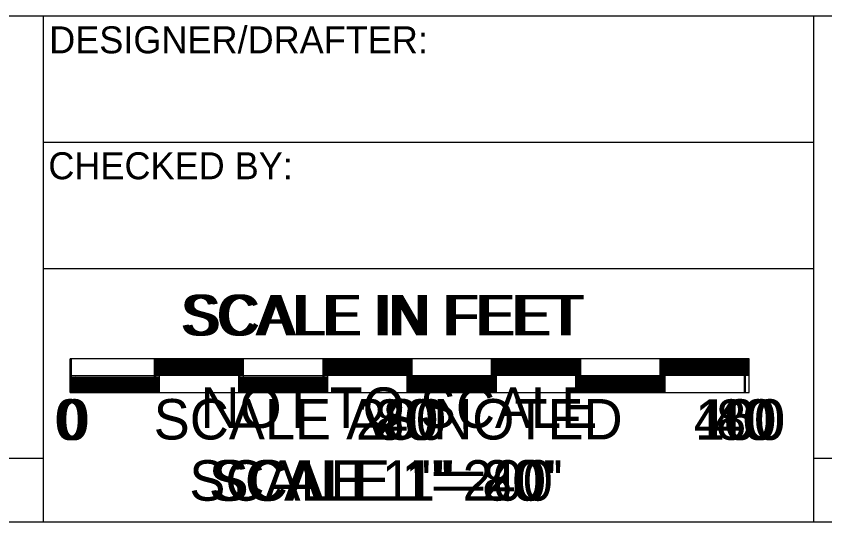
# Model space of a CAD drawing. Extents: x 0 to 2011, y -71 to 1183.
# Drawn here: x 341.3 to 437.3, y -1 to 59 of the extents above; entities that cross this region are included whole.
import ezdxf

# ---------------------------------------------------------------- set-up
doc = ezdxf.new("R2010")
doc.units = 0
for name, color, linetype in [('CT_Border_Perimeter_Shape', 7, 'Continuous'), ('CT_Scale_1_Inch_Equals_200_Feet', 7, 'Continuous'), ('CT_Scale_1_Inch_Equals_20_Feet', 7, 'Continuous'), ('CT_Scale_1_Inch_Equals_40_Feet', 7, 'Continuous'), ('CT_Scale_1_Inch_Equals_80_Feet', 7, 'Continuous'), ('CT_Scale_as_Noted', 7, 'Continuous'), ('CT_Title_Block_Linework', 7, 'Continuous'), ('CT_Title_Block_Text', 7, 'Continuous')]:
    doc.layers.add(name, color=color, linetype=linetype)

msp = doc.modelspace()

# ---------------------------------------------------------------- linework, layer by layer
at = {"layer": 'CT_Border_Perimeter_Shape'}
msp.add_lwpolyline([(0, -0.973), (1270, -0.973), (1270, 829.027), (0, 829.027)], close=True, dxfattribs=at)
at = {"layer": 'CT_Scale_1_Inch_Equals_200_Feet'}
for p, q in [((427.743, 18.378), (347.743, 18.378)), ((347.743, 14.384), (347.743, 18.378)), ((357.743, 14.385), (357.743, 18.378)), ((367.743, 18.242), (357.743, 18.242)), ((367.743, 14.385), (367.743, 18.378)), ((377.743, 14.386), (377.743, 18.378)), ((387.743, 18.242), (377.743, 18.242)), ((387.743, 14.398), (387.743, 18.378)), ((397.743, 14.398), (397.743, 18.378)), ((407.743, 18.254), (397.743, 18.254)), ((407.743, 14.388), (407.743, 18.378)), ((417.743, 14.389), (417.743, 18.378)), ((427.743, 18.254), (417.743, 18.254)), ((427.743, 14.39), (427.743, 18.378)), ((367.743, 18.118), (357.743, 18.118)), ((367.743, 17.994), (357.743, 17.994)), ((367.743, 17.87), (357.743, 17.87)), ((367.743, 17.742), (357.743, 17.742)), ((367.743, 17.618), (357.743, 17.618)), ((367.743, 17.494), (357.743, 17.494)), ((367.743, 17.37), (357.743, 17.37)), ((387.743, 18.118), (377.743, 18.118)), ((387.743, 17.994), (377.743, 17.994)), ((387.743, 17.87), (377.743, 17.87)), ((387.743, 17.742), (377.743, 17.742)), ((387.743, 17.618), (377.743, 17.618)), ((387.743, 17.494), (377.743, 17.494)), ((387.743, 17.37), (377.743, 17.37)), ((407.743, 18.13), (397.743, 18.13)), ((407.743, 18.002), (397.743, 18.002)), ((407.743, 17.878), (397.743, 17.878)), ((407.743, 17.754), (397.743, 17.754)), ((407.743, 17.63), (397.743, 17.63)), ((407.743, 17.502), (397.743, 17.502)), ((407.743, 17.378), (397.743, 17.378)), ((427.743, 18.13), (417.743, 18.13)), ((427.743, 18.002), (417.743, 18.002)), ((427.743, 17.878), (417.743, 17.878)), ((427.743, 17.878), (417.743, 17.878)), ((427.743, 17.754), (417.743, 17.754)), ((427.743, 17.63), (417.743, 17.63)), ((427.743, 17.502), (417.743, 17.502)), ((427.743, 17.378), (417.743, 17.378)), ((427.743, 16.39), (347.743, 16.364)), ((367.743, 17.242), (357.743, 17.242)), ((367.743, 17.118), (357.743, 17.118)), ((367.743, 16.994), (357.743, 16.994)), ((367.743, 16.87), (357.743, 16.87)), ((367.743, 16.742), (357.743, 16.742)), ((367.743, 16.618), (357.743, 16.618)), ((367.743, 16.494), (357.743, 16.494)), ((387.743, 17.242), (377.743, 17.242)), ((387.743, 17.118), (377.743, 17.118)), ((387.743, 16.994), (377.743, 16.994)), ((387.743, 16.87), (377.743, 16.87)), ((387.743, 16.742), (377.743, 16.742)), ((387.743, 16.618), (377.743, 16.618)), ((387.743, 16.494), (377.743, 16.494)), ((407.743, 17.254), (397.743, 17.254)), ((407.743, 17.13), (397.743, 17.13)), ((407.743, 17.002), (397.743, 17.002)), ((407.743, 16.878), (397.743, 16.878)), ((407.743, 16.754), (397.743, 16.754)), ((407.743, 16.63), (397.743, 16.63)), ((407.743, 16.502), (397.743, 16.502)), ((427.743, 17.254), (417.743, 17.254)), ((427.743, 17.13), (417.743, 17.13)), ((427.743, 17.002), (417.743, 17.002)), ((427.743, 16.878), (417.743, 16.878)), ((427.743, 16.754), (417.743, 16.754)), ((427.743, 16.63), (417.743, 16.63)), ((427.743, 16.502), (417.743, 16.502)), ((347.743, 16.242), (357.743, 16.242)), ((347.743, 16.118), (357.743, 16.118)), ((347.743, 15.994), (357.743, 15.994)), ((347.743, 15.87), (357.743, 15.87)), ((347.743, 15.742), (357.743, 15.742)), ((347.743, 15.618), (357.743, 15.618)), ((347.743, 15.494), (357.743, 15.494)), ((347.743, 15.37), (357.743, 15.37)), ((367.743, 16.242), (377.743, 16.242)), ((367.743, 16.118), (377.743, 16.118)), ((367.743, 15.994), (377.743, 15.994)), ((367.743, 15.87), (377.743, 15.87)), ((367.743, 15.742), (377.743, 15.742)), ((367.743, 15.618), (377.743, 15.618)), ((367.743, 15.494), (377.743, 15.494)), ((367.743, 15.37), (377.743, 15.37)), ((397.743, 16.256), (387.743, 16.256)), ((397.743, 16.132), (387.743, 16.132)), ((397.743, 16.004), (387.743, 16.004)), ((397.743, 15.88), (387.743, 15.88)), ((397.743, 15.88), (387.743, 15.88)), ((397.743, 15.756), (387.743, 15.756)), ((397.743, 15.632), (387.743, 15.632)), ((397.743, 15.504), (387.743, 15.504)), ((397.743, 15.38), (387.743, 15.38)), ((407.743, 16.254), (417.743, 16.254)), ((407.743, 16.13), (417.743, 16.13)), ((407.743, 16.002), (417.743, 16.002)), ((407.743, 15.878), (417.743, 15.878)), ((407.743, 15.754), (417.743, 15.754)), ((407.743, 15.63), (417.743, 15.63)), ((407.743, 15.502), (417.743, 15.502)), ((407.743, 15.378), (417.743, 15.378)), ((347.743, 15.242), (357.743, 15.242)), ((347.743, 15.118), (357.743, 15.118)), ((347.743, 14.994), (357.743, 14.994)), ((347.743, 14.87), (357.743, 14.87)), ((347.743, 14.742), (357.743, 14.742)), ((347.743, 14.618), (357.743, 14.618)), ((347.743, 14.494), (357.743, 14.494)), ((367.743, 15.242), (377.743, 15.242)), ((367.743, 15.118), (377.743, 15.118)), ((367.743, 14.994), (377.743, 14.994)), ((367.743, 14.87), (377.743, 14.87)), ((367.743, 14.742), (377.743, 14.742)), ((367.743, 14.618), (377.743, 14.618)), ((367.743, 14.494), (377.743, 14.494)), ((397.743, 15.256), (387.743, 15.256)), ((397.743, 15.132), (387.743, 15.132)), ((397.743, 15.004), (387.743, 15.004)), ((397.743, 14.88), (387.743, 14.88)), ((397.743, 14.756), (387.743, 14.756)), ((397.743, 14.632), (387.743, 14.632)), ((397.743, 14.504), (387.743, 14.504)), ((407.743, 15.254), (417.743, 15.254)), ((407.743, 15.13), (417.743, 15.13)), ((407.743, 15.002), (417.743, 15.002)), ((407.743, 14.878), (417.743, 14.878)), ((407.743, 14.754), (417.743, 14.754)), ((407.743, 14.63), (417.743, 14.63)), ((407.743, 14.502), (417.743, 14.502)), ((347.743, 14.384), (427.743, 14.39))]:
    msp.add_line(p, q, dxfattribs=at)
at = {"layer": 'CT_Scale_1_Inch_Equals_20_Feet'}
for p, q in [((427.888, 18.378), (347.888, 18.378)), ((347.888, 14.384), (347.888, 18.378)), ((357.888, 14.385), (357.888, 18.378)), ((367.888, 18.242), (357.888, 18.242)), ((367.888, 14.385), (367.888, 18.378)), ((377.888, 14.386), (377.888, 18.378)), ((387.888, 18.242), (377.888, 18.242)), ((387.888, 14.398), (387.888, 18.378)), ((397.888, 14.398), (397.888, 18.378)), ((407.888, 18.254), (397.888, 18.254)), ((407.888, 14.388), (407.888, 18.378)), ((417.888, 14.389), (417.888, 18.378)), ((427.888, 18.254), (417.888, 18.254)), ((427.888, 14.39), (427.888, 18.378)), ((367.888, 18.118), (357.888, 18.118)), ((367.888, 17.994), (357.888, 17.994)), ((367.888, 17.87), (357.888, 17.87)), ((367.888, 17.742), (357.888, 17.742)), ((367.888, 17.618), (357.888, 17.618)), ((367.888, 17.494), (357.888, 17.494)), ((367.888, 17.37), (357.888, 17.37)), ((387.888, 18.118), (377.888, 18.118)), ((387.888, 17.994), (377.888, 17.994)), ((387.888, 17.87), (377.888, 17.87)), ((387.888, 17.742), (377.888, 17.742)), ((387.888, 17.618), (377.888, 17.618)), ((387.888, 17.494), (377.888, 17.494)), ((387.888, 17.37), (377.888, 17.37)), ((407.888, 18.13), (397.888, 18.13)), ((407.888, 18.002), (397.888, 18.002)), ((407.888, 17.878), (397.888, 17.878)), ((407.888, 17.754), (397.888, 17.754)), ((407.888, 17.63), (397.888, 17.63)), ((407.888, 17.502), (397.888, 17.502)), ((407.888, 17.378), (397.888, 17.378)), ((427.888, 18.13), (417.888, 18.13)), ((427.888, 18.002), (417.888, 18.002)), ((427.888, 17.878), (417.888, 17.878)), ((427.888, 17.878), (417.888, 17.878)), ((427.888, 17.754), (417.888, 17.754)), ((427.888, 17.63), (417.888, 17.63)), ((427.888, 17.502), (417.888, 17.502)), ((427.888, 17.378), (417.888, 17.378)), ((427.888, 16.39), (347.888, 16.364)), ((367.888, 17.242), (357.888, 17.242)), ((367.888, 17.118), (357.888, 17.118)), ((367.888, 16.994), (357.888, 16.994)), ((367.888, 16.87), (357.888, 16.87)), ((367.888, 16.742), (357.888, 16.742)), ((367.888, 16.618), (357.888, 16.618)), ((367.888, 16.494), (357.888, 16.494)), ((387.888, 17.242), (377.888, 17.242)), ((387.888, 17.118), (377.888, 17.118)), ((387.888, 16.994), (377.888, 16.994)), ((387.888, 16.87), (377.888, 16.87)), ((387.888, 16.742), (377.888, 16.742)), ((387.888, 16.618), (377.888, 16.618)), ((387.888, 16.494), (377.888, 16.494)), ((407.888, 17.254), (397.888, 17.254)), ((407.888, 17.13), (397.888, 17.13)), ((407.888, 17.002), (397.888, 17.002)), ((407.888, 16.878), (397.888, 16.878)), ((407.888, 16.754), (397.888, 16.754)), ((407.888, 16.63), (397.888, 16.63)), ((407.888, 16.502), (397.888, 16.502)), ((427.888, 17.254), (417.888, 17.254)), ((427.888, 17.13), (417.888, 17.13)), ((427.888, 17.002), (417.888, 17.002)), ((427.888, 16.878), (417.888, 16.878)), ((427.888, 16.754), (417.888, 16.754)), ((427.888, 16.63), (417.888, 16.63)), ((427.888, 16.502), (417.888, 16.502)), ((347.888, 16.242), (357.888, 16.242)), ((347.888, 16.118), (357.888, 16.118)), ((347.888, 15.994), (357.888, 15.994)), ((347.888, 15.87), (357.888, 15.87)), ((347.888, 15.742), (357.888, 15.742)), ((347.888, 15.618), (357.888, 15.618)), ((347.888, 15.494), (357.888, 15.494)), ((347.888, 15.37), (357.888, 15.37)), ((367.888, 16.242), (377.888, 16.242)), ((367.888, 16.118), (377.888, 16.118)), ((367.888, 15.994), (377.888, 15.994)), ((367.888, 15.87), (377.888, 15.87)), ((367.888, 15.742), (377.888, 15.742)), ((367.888, 15.618), (377.888, 15.618)), ((367.888, 15.494), (377.888, 15.494)), ((367.888, 15.37), (377.888, 15.37)), ((397.888, 16.256), (387.888, 16.256)), ((397.888, 16.132), (387.888, 16.132)), ((397.888, 16.004), (387.888, 16.004)), ((397.888, 15.88), (387.888, 15.88)), ((397.888, 15.88), (387.888, 15.88)), ((397.888, 15.756), (387.888, 15.756)), ((397.888, 15.632), (387.888, 15.632)), ((397.888, 15.504), (387.888, 15.504)), ((397.888, 15.38), (387.888, 15.38)), ((407.888, 16.254), (417.888, 16.254)), ((407.888, 16.13), (417.888, 16.13)), ((407.888, 16.002), (417.888, 16.002)), ((407.888, 15.878), (417.888, 15.878)), ((407.888, 15.754), (417.888, 15.754)), ((407.888, 15.63), (417.888, 15.63)), ((407.888, 15.502), (417.888, 15.502)), ((407.888, 15.378), (417.888, 15.378)), ((347.888, 15.242), (357.888, 15.242)), ((347.888, 15.118), (357.888, 15.118)), ((347.888, 14.994), (357.888, 14.994)), ((347.888, 14.87), (357.888, 14.87)), ((347.888, 14.742), (357.888, 14.742)), ((347.888, 14.618), (357.888, 14.618)), ((347.888, 14.494), (357.888, 14.494)), ((367.888, 15.242), (377.888, 15.242)), ((367.888, 15.118), (377.888, 15.118)), ((367.888, 14.994), (377.888, 14.994)), ((367.888, 14.87), (377.888, 14.87)), ((367.888, 14.742), (377.888, 14.742)), ((367.888, 14.618), (377.888, 14.618)), ((367.888, 14.494), (377.888, 14.494)), ((397.888, 15.256), (387.888, 15.256)), ((397.888, 15.132), (387.888, 15.132)), ((397.888, 15.004), (387.888, 15.004)), ((397.888, 14.88), (387.888, 14.88)), ((397.888, 14.756), (387.888, 14.756)), ((397.888, 14.632), (387.888, 14.632)), ((397.888, 14.504), (387.888, 14.504)), ((407.888, 15.254), (417.888, 15.254)), ((407.888, 15.13), (417.888, 15.13)), ((407.888, 15.002), (417.888, 15.002)), ((407.888, 14.878), (417.888, 14.878)), ((407.888, 14.754), (417.888, 14.754)), ((407.888, 14.63), (417.888, 14.63)), ((407.888, 14.502), (417.888, 14.502)), ((347.888, 14.384), (427.888, 14.39))]:
    msp.add_line(p, q, dxfattribs=at)
at = {"layer": 'CT_Scale_1_Inch_Equals_40_Feet'}
for p, q in [((428.32, 18.378), (348.32, 18.378)), ((358.32, 14.385), (358.32, 18.378)), ((368.32, 18.242), (358.32, 18.242)), ((368.32, 14.385), (368.32, 18.378)), ((378.32, 14.386), (378.32, 18.378)), ((388.32, 18.242), (378.32, 18.242)), ((388.32, 14.398), (388.32, 18.378)), ((398.32, 14.398), (398.32, 18.378)), ((408.32, 18.254), (398.32, 18.254)), ((408.32, 14.388), (408.32, 18.378)), ((418.32, 14.389), (418.32, 18.378)), ((428.32, 18.254), (418.32, 18.254)), ((428.32, 14.39), (428.32, 18.378)), ((368.32, 18.118), (358.32, 18.118)), ((368.32, 17.994), (358.32, 17.994)), ((368.32, 17.87), (358.32, 17.87)), ((368.32, 17.742), (358.32, 17.742)), ((368.32, 17.618), (358.32, 17.618)), ((368.32, 17.494), (358.32, 17.494)), ((368.32, 17.37), (358.32, 17.37)), ((388.32, 18.118), (378.32, 18.118)), ((388.32, 17.994), (378.32, 17.994)), ((388.32, 17.87), (378.32, 17.87)), ((388.32, 17.742), (378.32, 17.742)), ((388.32, 17.618), (378.32, 17.618)), ((388.32, 17.494), (378.32, 17.494)), ((388.32, 17.37), (378.32, 17.37)), ((408.32, 18.13), (398.32, 18.13)), ((408.32, 18.002), (398.32, 18.002)), ((408.32, 17.878), (398.32, 17.878)), ((408.32, 17.754), (398.32, 17.754)), ((408.32, 17.63), (398.32, 17.63)), ((408.32, 17.502), (398.32, 17.502)), ((408.32, 17.378), (398.32, 17.378)), ((428.32, 18.13), (418.32, 18.13)), ((428.32, 18.002), (418.32, 18.002)), ((428.32, 17.878), (418.32, 17.878)), ((428.32, 17.878), (418.32, 17.878)), ((428.32, 17.754), (418.32, 17.754)), ((428.32, 17.63), (418.32, 17.63)), ((428.32, 17.502), (418.32, 17.502)), ((428.32, 17.378), (418.32, 17.378)), ((428.32, 16.39), (348.32, 16.364)), ((368.32, 17.242), (358.32, 17.242)), ((368.32, 17.118), (358.32, 17.118)), ((368.32, 16.994), (358.32, 16.994)), ((368.32, 16.87), (358.32, 16.87)), ((368.32, 16.742), (358.32, 16.742)), ((368.32, 16.618), (358.32, 16.618)), ((368.32, 16.494), (358.32, 16.494)), ((388.32, 17.242), (378.32, 17.242)), ((388.32, 17.118), (378.32, 17.118)), ((388.32, 16.994), (378.32, 16.994)), ((388.32, 16.87), (378.32, 16.87)), ((388.32, 16.742), (378.32, 16.742)), ((388.32, 16.618), (378.32, 16.618)), ((388.32, 16.494), (378.32, 16.494)), ((408.32, 17.254), (398.32, 17.254)), ((408.32, 17.13), (398.32, 17.13)), ((408.32, 17.002), (398.32, 17.002)), ((408.32, 16.878), (398.32, 16.878)), ((408.32, 16.754), (398.32, 16.754)), ((408.32, 16.63), (398.32, 16.63)), ((408.32, 16.502), (398.32, 16.502)), ((428.32, 17.254), (418.32, 17.254)), ((428.32, 17.13), (418.32, 17.13)), ((428.32, 17.002), (418.32, 17.002)), ((428.32, 16.878), (418.32, 16.878)), ((428.32, 16.754), (418.32, 16.754)), ((428.32, 16.63), (418.32, 16.63)), ((428.32, 16.502), (418.32, 16.502)), ((348.32, 16.242), (358.32, 16.242)), ((348.32, 16.118), (358.32, 16.118)), ((348.32, 15.994), (358.32, 15.994)), ((348.32, 15.87), (358.32, 15.87)), ((348.32, 15.742), (358.32, 15.742)), ((348.32, 15.618), (358.32, 15.618)), ((348.32, 15.494), (358.32, 15.494)), ((348.32, 15.37), (358.32, 15.37)), ((368.32, 16.242), (378.32, 16.242)), ((368.32, 16.118), (378.32, 16.118)), ((368.32, 15.994), (378.32, 15.994)), ((368.32, 15.87), (378.32, 15.87)), ((368.32, 15.742), (378.32, 15.742)), ((368.32, 15.618), (378.32, 15.618)), ((368.32, 15.494), (378.32, 15.494)), ((368.32, 15.37), (378.32, 15.37)), ((398.32, 16.256), (388.32, 16.256)), ((398.32, 16.132), (388.32, 16.132)), ((398.32, 16.004), (388.32, 16.004)), ((398.32, 15.88), (388.32, 15.88)), ((398.32, 15.88), (388.32, 15.88)), ((398.32, 15.756), (388.32, 15.756)), ((398.32, 15.632), (388.32, 15.632)), ((398.32, 15.504), (388.32, 15.504)), ((398.32, 15.38), (388.32, 15.38)), ((408.32, 16.254), (418.32, 16.254)), ((408.32, 16.13), (418.32, 16.13)), ((408.32, 16.002), (418.32, 16.002)), ((408.32, 15.878), (418.32, 15.878)), ((408.32, 15.754), (418.32, 15.754)), ((408.32, 15.63), (418.32, 15.63)), ((408.32, 15.502), (418.32, 15.502)), ((408.32, 15.378), (418.32, 15.378)), ((348.32, 15.242), (358.32, 15.242)), ((348.32, 15.118), (358.32, 15.118)), ((348.32, 14.994), (358.32, 14.994)), ((348.32, 14.87), (358.32, 14.87)), ((348.32, 14.742), (358.32, 14.742)), ((348.32, 14.618), (358.32, 14.618)), ((348.32, 14.494), (358.32, 14.494)), ((368.32, 15.242), (378.32, 15.242)), ((368.32, 15.118), (378.32, 15.118)), ((368.32, 14.994), (378.32, 14.994)), ((368.32, 14.87), (378.32, 14.87)), ((368.32, 14.742), (378.32, 14.742)), ((368.32, 14.618), (378.32, 14.618)), ((368.32, 14.494), (378.32, 14.494)), ((398.32, 15.256), (388.32, 15.256)), ((398.32, 15.132), (388.32, 15.132)), ((398.32, 15.004), (388.32, 15.004)), ((398.32, 14.88), (388.32, 14.88)), ((398.32, 14.756), (388.32, 14.756)), ((398.32, 14.632), (388.32, 14.632)), ((398.32, 14.504), (388.32, 14.504)), ((408.32, 15.254), (418.32, 15.254)), ((408.32, 15.13), (418.32, 15.13)), ((408.32, 15.002), (418.32, 15.002)), ((408.32, 14.878), (418.32, 14.878)), ((408.32, 14.754), (418.32, 14.754)), ((408.32, 14.63), (418.32, 14.63)), ((408.32, 14.502), (418.32, 14.502)), ((348.32, 14.384), (428.32, 14.39))]:
    msp.add_line(p, q, dxfattribs=at)
at = {"layer": 'CT_Scale_1_Inch_Equals_80_Feet'}
for p, q in [((427.88, 18.378), (347.88, 18.378)), ((347.88, 14.384), (347.88, 18.378)), ((357.88, 14.385), (357.88, 18.378)), ((367.88, 18.242), (357.88, 18.242)), ((367.88, 14.385), (367.88, 18.378)), ((377.88, 14.386), (377.88, 18.378)), ((387.88, 18.242), (377.88, 18.242)), ((387.88, 14.398), (387.88, 18.378)), ((397.88, 14.398), (397.88, 18.378)), ((407.88, 18.254), (397.88, 18.254)), ((407.88, 14.388), (407.88, 18.378)), ((417.88, 14.389), (417.88, 18.378)), ((427.88, 18.254), (417.88, 18.254)), ((427.88, 14.39), (427.88, 18.378)), ((367.88, 18.118), (357.88, 18.118)), ((367.88, 17.994), (357.88, 17.994)), ((367.88, 17.87), (357.88, 17.87)), ((367.88, 17.742), (357.88, 17.742)), ((367.88, 17.618), (357.88, 17.618)), ((367.88, 17.494), (357.88, 17.494)), ((367.88, 17.37), (357.88, 17.37)), ((387.88, 18.118), (377.88, 18.118)), ((387.88, 17.994), (377.88, 17.994)), ((387.88, 17.87), (377.88, 17.87)), ((387.88, 17.742), (377.88, 17.742)), ((387.88, 17.618), (377.88, 17.618)), ((387.88, 17.494), (377.88, 17.494)), ((387.88, 17.37), (377.88, 17.37)), ((407.88, 18.13), (397.88, 18.13)), ((407.88, 18.002), (397.88, 18.002)), ((407.88, 17.878), (397.88, 17.878)), ((407.88, 17.754), (397.88, 17.754)), ((407.88, 17.63), (397.88, 17.63)), ((407.88, 17.502), (397.88, 17.502)), ((407.88, 17.378), (397.88, 17.378)), ((427.88, 18.13), (417.88, 18.13)), ((427.88, 18.002), (417.88, 18.002)), ((427.88, 17.878), (417.88, 17.878)), ((427.88, 17.878), (417.88, 17.878)), ((427.88, 17.754), (417.88, 17.754)), ((427.88, 17.63), (417.88, 17.63)), ((427.88, 17.502), (417.88, 17.502)), ((427.88, 17.378), (417.88, 17.378)), ((427.88, 16.39), (347.88, 16.364)), ((367.88, 17.242), (357.88, 17.242)), ((367.88, 17.118), (357.88, 17.118)), ((367.88, 16.994), (357.88, 16.994)), ((367.88, 16.87), (357.88, 16.87)), ((367.88, 16.742), (357.88, 16.742)), ((367.88, 16.618), (357.88, 16.618)), ((367.88, 16.494), (357.88, 16.494)), ((387.88, 17.242), (377.88, 17.242)), ((387.88, 17.118), (377.88, 17.118)), ((387.88, 16.994), (377.88, 16.994)), ((387.88, 16.87), (377.88, 16.87)), ((387.88, 16.742), (377.88, 16.742)), ((387.88, 16.618), (377.88, 16.618)), ((387.88, 16.494), (377.88, 16.494)), ((407.88, 17.254), (397.88, 17.254)), ((407.88, 17.13), (397.88, 17.13)), ((407.88, 17.002), (397.88, 17.002)), ((407.88, 16.878), (397.88, 16.878)), ((407.88, 16.754), (397.88, 16.754)), ((407.88, 16.63), (397.88, 16.63)), ((407.88, 16.502), (397.88, 16.502)), ((427.88, 17.254), (417.88, 17.254)), ((427.88, 17.13), (417.88, 17.13)), ((427.88, 17.002), (417.88, 17.002)), ((427.88, 16.878), (417.88, 16.878)), ((427.88, 16.754), (417.88, 16.754)), ((427.88, 16.63), (417.88, 16.63)), ((427.88, 16.502), (417.88, 16.502)), ((347.88, 16.242), (357.88, 16.242)), ((347.88, 16.118), (357.88, 16.118)), ((347.88, 15.994), (357.88, 15.994)), ((347.88, 15.87), (357.88, 15.87)), ((347.88, 15.742), (357.88, 15.742)), ((347.88, 15.618), (357.88, 15.618)), ((347.88, 15.494), (357.88, 15.494)), ((347.88, 15.37), (357.88, 15.37)), ((367.88, 16.242), (377.88, 16.242)), ((367.88, 16.118), (377.88, 16.118)), ((367.88, 15.994), (377.88, 15.994)), ((367.88, 15.87), (377.88, 15.87)), ((367.88, 15.742), (377.88, 15.742)), ((367.88, 15.618), (377.88, 15.618)), ((367.88, 15.494), (377.88, 15.494)), ((367.88, 15.37), (377.88, 15.37)), ((397.88, 16.256), (387.88, 16.256)), ((397.88, 16.132), (387.88, 16.132)), ((397.88, 16.004), (387.88, 16.004)), ((397.88, 15.88), (387.88, 15.88)), ((397.88, 15.88), (387.88, 15.88)), ((397.88, 15.756), (387.88, 15.756)), ((397.88, 15.632), (387.88, 15.632)), ((397.88, 15.504), (387.88, 15.504)), ((397.88, 15.38), (387.88, 15.38)), ((407.88, 16.254), (417.88, 16.254)), ((407.88, 16.13), (417.88, 16.13)), ((407.88, 16.002), (417.88, 16.002)), ((407.88, 15.878), (417.88, 15.878)), ((407.88, 15.754), (417.88, 15.754)), ((407.88, 15.63), (417.88, 15.63)), ((407.88, 15.502), (417.88, 15.502)), ((407.88, 15.378), (417.88, 15.378)), ((347.88, 15.242), (357.88, 15.242)), ((347.88, 15.118), (357.88, 15.118)), ((347.88, 14.994), (357.88, 14.994)), ((347.88, 14.87), (357.88, 14.87)), ((347.88, 14.742), (357.88, 14.742)), ((347.88, 14.618), (357.88, 14.618)), ((347.88, 14.494), (357.88, 14.494)), ((367.88, 15.242), (377.88, 15.242)), ((367.88, 15.118), (377.88, 15.118)), ((367.88, 14.994), (377.88, 14.994)), ((367.88, 14.87), (377.88, 14.87)), ((367.88, 14.742), (377.88, 14.742)), ((367.88, 14.618), (377.88, 14.618)), ((367.88, 14.494), (377.88, 14.494)), ((397.88, 15.256), (387.88, 15.256)), ((397.88, 15.132), (387.88, 15.132)), ((397.88, 15.004), (387.88, 15.004)), ((397.88, 14.88), (387.88, 14.88)), ((397.88, 14.756), (387.88, 14.756)), ((397.88, 14.632), (387.88, 14.632)), ((397.88, 14.504), (387.88, 14.504)), ((407.88, 15.254), (417.88, 15.254)), ((407.88, 15.13), (417.88, 15.13)), ((407.88, 15.002), (417.88, 15.002)), ((407.88, 14.878), (417.88, 14.878)), ((407.88, 14.754), (417.88, 14.754)), ((407.88, 14.63), (417.88, 14.63)), ((407.88, 14.502), (417.88, 14.502)), ((347.88, 14.384), (427.88, 14.39))]:
    msp.add_line(p, q, dxfattribs=at)
at = {"layer": 'CT_Title_Block_Linework'}
for p, q in [((1270, 59.027), (0, 59.027)), ((344.549, 59.027), (344.549, -0.973)), ((435.948, 59.027), (435.948, -0.973)), ((435.948, 44.027), (344.549, 44.027)), ((435.948, 29.027), (344.549, 29.027)), ((344.549, 6.527), (0, 6.527)), ((651.861, 6.527), (435.948, 6.527))]:
    msp.add_line(p, q, dxfattribs=at)

# ---------------------------------------------------------------- texts
at = {"layer": 'CT_Border_Perimeter_Shape'}
msp.add_text('NOT TO SCALE', height=4.8, dxfattribs=at).set_placement((363.195, 10.172))
at = {"layer": 'CT_Scale_1_Inch_Equals_200_Feet'}
for s, p in [('SCALE IN FEET', (360.792, 21.151)), ('0', (345.886, 8.757)), ('200', (381.63, 8.757)), ('400', (421.741, 8.757))]:
    msp.add_text(s, height=4.8, dxfattribs=at).set_placement(p)
msp.add_text('SCALE 1"=200\'', height=4.8, rotation=0.01259, dxfattribs=at).set_placement((361.876, 1.532))
at = {"layer": 'CT_Scale_1_Inch_Equals_20_Feet'}
for s, p in [('SCALE IN FEET', (360.938, 21.151)), ('0', (346.032, 8.757)), ('20', (383.849, 8.757)), ('40', (423.96, 8.757))]:
    msp.add_text(s, height=4.8, dxfattribs=at).set_placement(p)
msp.add_text('SCALE 1"=20\'', height=4.8, rotation=0.01259, dxfattribs=at).set_placement((364.205, 1.533))
at = {"layer": 'CT_Scale_1_Inch_Equals_40_Feet'}
for s, rotation, p in [('SCALE IN FEET', 360, (361.369, 21.151)), ('0', 360, (346.463, 8.757)), ('40', 360, (384.28, 8.757)), ('80', 360, (424.391, 8.757)), ('SCALE 1"=40\'', 0.01259, (364.636, 1.533))]:
    msp.add_text(s, height=4.8, rotation=rotation, dxfattribs=at).set_placement(p)
at = {"layer": 'CT_Scale_1_Inch_Equals_80_Feet'}
for s, p in [('SCALE IN FEET', (360.929, 21.151)), ('0', (346.024, 8.757)), ('80', (383.841, 8.757)), ('160', (421.879, 8.757))]:
    msp.add_text(s, height=4.8, dxfattribs=at).set_placement(p)
msp.add_text('SCALE 1"=80\'', height=4.8, rotation=0.01259, dxfattribs=at).set_placement((364.197, 1.533))
at = {"layer": 'CT_Scale_as_Noted'}
msp.add_text('SCALE AS NOTED', height=4.8, dxfattribs=at).set_placement((357.647, 8.796))
at = {"layer": 'CT_Title_Block_Text'}
for s, p in [('DESIGNER/DRAFTER:', (345.249, 54.619)), ('CHECKED BY:', (345.147, 39.677))]:
    msp.add_text(s, height=3.2, rotation=360, dxfattribs=at).set_placement(p)

doc.saveas('drawing.dxf')
